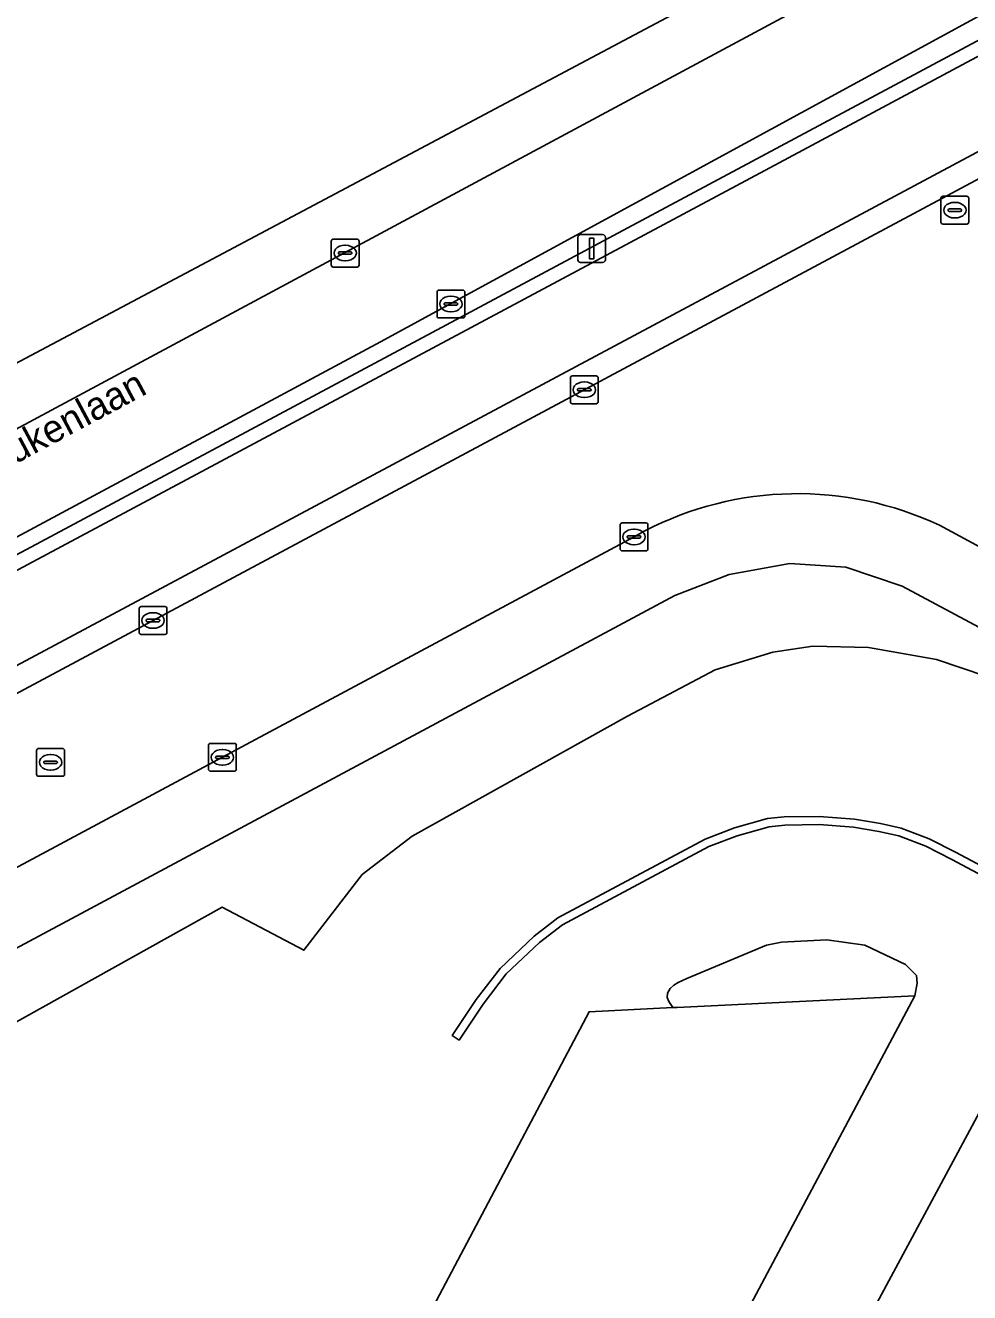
# Model space of a CAD drawing. Extents: x 159489 to 160304, y 383825 to 384531.
# Drawn here: x 159655.5 to 159689.39, y 384375.44 to 384420.89 of the extents above; entities that cross this region are included whole.
import ezdxf

# ---------------------------------------------------------------- set-up
doc = ezdxf.new("R2010")
doc.units = 0
for name, color, linetype in [('IMGEO_Berm_open', 7, 'Continuous'), ('IMGEO_Fietspad_gesloten', 7, 'Continuous'), ('IMGEO_Groenvoorziening', 7, 'Continuous'), ('IMGEO_Kolk', 7, 'Continuous'), ('IMGEO_Lichtmast', 7, 'Continuous'), ('IMGEO_Openbare_ruimte_label', 7, 'Continuous'), ('IMGEO_Parkeervlak_gesloten', 7, 'Continuous'), ('IMGEO_Rijbaan_lokaal_gesloten', 7, 'Continuous'), ('IMGEO_Rijbaan_lokaal_open', 7, 'Continuous'), ('IMGEO_Rijbaan_regionaal_gesloten', 7, 'Continuous'), ('IMGEO_Rioolput', 7, 'Continuous'), ('IMGEO_Verkeerseiland_open', 7, 'Continuous'), ('IMGEO_Voetpad_open', 7, 'Continuous')]:
    doc.layers.add(name, color=color, linetype=linetype)

msp = doc.modelspace()

# ---------------------------------------------------------------- linework, layer by layer
at = {"layer": 'IMGEO_Berm_open'}
for points in [[(159700.571, 384426.18), (159700.198, 384426.93), (159699.377, 384426.484), (159668.244, 384409.54), (159634.421, 384391.406), (159619.966, 384383.61), (159620.115, 384383.333), (159655.541, 384402.086)], [(159682.221, 384415.781), (159700.906, 384425.794), (159700.323, 384426.977), (159700.198, 384426.93), (159700.571, 384426.18), (159655.541, 384402.086), (159620.115, 384383.333), (159620.424, 384382.758), (159622.046, 384383.628)]]:
    msp.add_lwpolyline(points, close=True, dxfattribs=at)
at = {"layer": 'IMGEO_Fietspad_gesloten'}
for points in [[(159700.906, 384425.794), (159682.221, 384415.781), (159622.046, 384383.628), (159620.424, 384382.758), (159619.93, 384382.493), (159571.207, 384356.355), (159556.599, 384348.661)], [(159562.194, 384348.219), (159572.535, 384353.778), (159693.459, 384418.367)]]:
    msp.add_lwpolyline(points, dxfattribs=at)
at = {"layer": 'IMGEO_Groenvoorziening'}
for points in [[(159711.661, 384387.572), (159686.961, 384400.768), (159684.938, 384401.459), (159682.928, 384401.583), (159680.757, 384401.193), (159678.807, 384400.435), (159634.346, 384376.64)], [(159617.084, 384363.924), (159662.566, 384389.265), (159665.498, 384387.718), (159667.587, 384390.432), (159669.384, 384391.81), (159677.113, 384396.112), (159680.259, 384397.773), (159682.319, 384398.41), (159683.758, 384398.622), (159685.752, 384398.573), (159688.197, 384398.149), (159689.963, 384397.545)], [(159697.451, 384386.675), (159688.879, 384391.235), (159687.93, 384391.716), (159686.929, 384392.101), (159686.185, 384392.267), (159685.248, 384392.421), (159683.99, 384392.517), (159682.735, 384392.498), (159682.132, 384392.44), (159680.952, 384392.107), (159679.9, 384391.703), (159674.611, 384388.882), (159673.759, 384388.225), (159672.537, 384387.065), (159671.685, 384385.957), (159670.821, 384384.662), (159671.067, 384384.497), (159671.926, 384385.785), (159672.758, 384386.867), (159673.951, 384388), (159674.772, 384388.632), (159680.023, 384391.433), (159681.045, 384391.826), (159682.187, 384392.148), (159682.752, 384392.202), (159683.981, 384392.221), (159685.213, 384392.127), (159686.128, 384391.977), (159686.843, 384391.816), (159687.809, 384391.445), (159688.743, 384390.972), (159697.314, 384386.412)]]:
    msp.add_lwpolyline(points, dxfattribs=at)
msp.add_lwpolyline([(159678.738, 384385.659), (159678.896, 384385.666), (159687.417, 384386.081), (159687.504, 384386.535), (159687.473, 384386.812), (159687.089, 384387.211), (159685.628, 384387.905), (159684.258, 384388.086), (159682.637, 384388.006), (159682.093, 384387.895), (159679.238, 384386.705), (159679.078, 384386.638), (159678.921, 384386.562), (159678.766, 384386.466), (159678.634, 384386.35), (159678.539, 384386.183), (159678.535, 384386.023), (159678.59, 384385.88)], close=True, dxfattribs=at)
at = {"layer": 'IMGEO_Kolk'}
for p, q in [((159670.274, 384410.465), (159670.274, 384411.317)), ((159670.349, 384411.391), (159671.201, 384411.391)), ((159671.275, 384411.317), (159671.275, 384410.465)), ((159670.533, 384410.885), (159670.533, 384410.897)), ((159670.971, 384410.848), (159670.573, 384410.848)), ((159670.576, 384410.934), (159670.974, 384410.934)), ((159670.762, 384411.171), (159670.787, 384411.171)), ((159671.017, 384410.897), (159671.017, 384410.885)), ((159671.201, 384410.391), (159670.349, 384410.391)), ((159670.785, 384410.611), (159670.76, 384410.611)), ((159675.058, 384407.39), (159675.058, 384408.242)), ((159675.133, 384408.316), (159675.985, 384408.316)), ((159676.059, 384408.242), (159676.059, 384407.39)), ((159675.317, 384407.81), (159675.317, 384407.822)), ((159675.755, 384407.773), (159675.357, 384407.773)), ((159675.36, 384407.859), (159675.758, 384407.859)), ((159675.546, 384408.096), (159675.571, 384408.096)), ((159675.801, 384407.822), (159675.801, 384407.81)), ((159675.985, 384407.316), (159675.133, 384407.316)), ((159675.569, 384407.536), (159675.544, 384407.536)), ((159676.842, 384402.113), (159676.842, 384402.965)), ((159676.917, 384403.039), (159677.769, 384403.039)), ((159677.33, 384402.819), (159677.355, 384402.819)), ((159677.843, 384402.965), (159677.843, 384402.113)), ((159677.101, 384402.533), (159677.101, 384402.545)), ((159677.539, 384402.496), (159677.141, 384402.496)), ((159677.144, 384402.582), (159677.542, 384402.582)), ((159677.353, 384402.259), (159677.328, 384402.259)), ((159677.585, 384402.545), (159677.585, 384402.533)), ((159677.769, 384402.039), (159676.917, 384402.039)), ((159659.584, 384399.116), (159659.584, 384399.968)), ((159659.659, 384400.042), (159660.511, 384400.042)), ((159660.585, 384399.968), (159660.585, 384399.116)), ((159659.843, 384399.536), (159659.843, 384399.548)), ((159660.281, 384399.499), (159659.883, 384399.499)), ((159659.886, 384399.585), (159660.284, 384399.585)), ((159660.072, 384399.822), (159660.097, 384399.822)), ((159660.327, 384399.548), (159660.327, 384399.536)), ((159660.511, 384399.042), (159659.659, 384399.042)), ((159660.095, 384399.262), (159660.07, 384399.262)), ((159662.073, 384394.21), (159662.073, 384395.062)), ((159662.148, 384395.136), (159663, 384395.136)), ((159663.074, 384395.062), (159663.074, 384394.21)), ((159662.332, 384394.63), (159662.332, 384394.642)), ((159662.77, 384394.593), (159662.372, 384394.593)), ((159662.375, 384394.679), (159662.773, 384394.679)), ((159662.561, 384394.916), (159662.586, 384394.916)), ((159662.816, 384394.642), (159662.816, 384394.63)), ((159663, 384394.136), (159662.148, 384394.136)), ((159662.584, 384394.356), (159662.559, 384394.356))]:
    msp.add_line(p, q, dxfattribs=at)
for points in [[(159670.274, 384410.465), (159670.274, 384411.317)], [(159670.349, 384411.391), (159671.201, 384411.391)], [(159671.275, 384411.317), (159671.275, 384410.465)], [(159671.201, 384410.391), (159670.349, 384410.391)], [(159675.058, 384407.39), (159675.058, 384408.242)], [(159675.133, 384408.316), (159675.985, 384408.316)], [(159676.059, 384408.242), (159676.059, 384407.39)], [(159675.985, 384407.316), (159675.133, 384407.316)], [(159676.842, 384402.113), (159676.842, 384402.965)], [(159676.917, 384403.039), (159677.769, 384403.039)], [(159677.843, 384402.965), (159677.843, 384402.113)], [(159677.769, 384402.039), (159676.917, 384402.039)], [(159659.584, 384399.116), (159659.584, 384399.968)], [(159659.659, 384400.042), (159660.511, 384400.042)], [(159660.585, 384399.968), (159660.585, 384399.116)], [(159660.511, 384399.042), (159659.659, 384399.042)], [(159662.073, 384394.21), (159662.073, 384395.062)], [(159662.148, 384395.136), (159663, 384395.136)], [(159663.074, 384395.062), (159663.074, 384394.21)], [(159663, 384394.136), (159662.148, 384394.136)]]:
    msp.add_lwpolyline(points, dxfattribs=at)
for centre, radius, start, end in [((159670.351, 384411.315), 0.0765, 91.552, 178.448), ((159670.351, 384411.315), 0.0765, 91.552, 178.448), ((159671.199, 384411.315), 0.0765, 1.552, 88.448), ((159671.199, 384411.315), 0.0765, 1.552, 88.448), ((159670.573, 384410.894), 0.0403, 85.8775, 175.7526), ((159670.57, 384410.884), 0.0366, 178.938, 274.7102), ((159670.974, 384410.891), 0.043, 264.8664, 352.4533), ((159670.978, 384410.896), 0.0386, 1.7309, 96.639), ((159670.351, 384410.467), 0.0765, 181.552, 268.448), ((159670.351, 384410.467), 0.0765, 181.552, 268.448), ((159671.199, 384410.467), 0.0765, 271.552, 358.448), ((159671.199, 384410.467), 0.0765, 271.552, 358.448), ((159675.135, 384408.24), 0.0765, 91.552, 178.448), ((159675.135, 384408.24), 0.0765, 91.552, 178.448), ((159675.983, 384408.24), 0.0765, 1.552, 88.448), ((159675.983, 384408.24), 0.0765, 1.552, 88.448), ((159675.357, 384407.819), 0.0403, 85.8775, 175.7526), ((159675.354, 384407.809), 0.0366, 178.938, 274.7102), ((159675.758, 384407.816), 0.043, 264.8664, 352.4533), ((159675.762, 384407.821), 0.0386, 1.7309, 96.639), ((159675.135, 384407.392), 0.0765, 181.552, 268.448), ((159675.135, 384407.392), 0.0765, 181.552, 268.448), ((159675.983, 384407.392), 0.0765, 271.552, 358.448), ((159675.983, 384407.392), 0.0765, 271.552, 358.448), ((159676.919, 384402.963), 0.0765, 91.552, 178.448), ((159676.919, 384402.963), 0.0765, 91.552, 178.448), ((159677.767, 384402.963), 0.0765, 1.552, 88.448), ((159677.767, 384402.963), 0.0765, 1.552, 88.448), ((159677.141, 384402.542), 0.0403, 85.8775, 175.7526), ((159677.138, 384402.532), 0.0366, 178.938, 274.7102), ((159677.542, 384402.539), 0.043, 264.8664, 352.4533), ((159677.546, 384402.544), 0.0386, 1.7309, 96.639), ((159676.919, 384402.115), 0.0765, 181.552, 268.448), ((159676.919, 384402.115), 0.0765, 181.552, 268.448), ((159677.767, 384402.115), 0.0765, 271.552, 358.448), ((159677.767, 384402.115), 0.0765, 271.552, 358.448), ((159659.661, 384399.966), 0.0765, 91.552, 178.448), ((159659.661, 384399.966), 0.0765, 91.552, 178.448), ((159660.509, 384399.966), 0.0765, 1.552, 88.448), ((159660.509, 384399.966), 0.0765, 1.552, 88.448), ((159659.883, 384399.545), 0.0403, 85.8775, 175.7526), ((159659.88, 384399.535), 0.0366, 178.938, 274.7102), ((159660.284, 384399.542), 0.043, 264.8664, 352.4533), ((159660.288, 384399.547), 0.0386, 1.7309, 96.639), ((159659.661, 384399.118), 0.0765, 181.552, 268.448), ((159659.661, 384399.118), 0.0765, 181.552, 268.448), ((159660.509, 384399.118), 0.0765, 271.552, 358.448), ((159660.509, 384399.118), 0.0765, 271.552, 358.448), ((159662.15, 384395.06), 0.0765, 91.552, 178.448), ((159662.15, 384395.06), 0.0765, 91.552, 178.448), ((159662.998, 384395.06), 0.0765, 1.552, 88.448), ((159662.998, 384395.06), 0.0765, 1.552, 88.448), ((159662.372, 384394.639), 0.0403, 85.8775, 175.7526), ((159662.369, 384394.629), 0.0366, 178.938, 274.7102), ((159662.773, 384394.636), 0.043, 264.8664, 352.4533), ((159662.777, 384394.641), 0.0386, 1.7309, 96.639), ((159662.15, 384394.212), 0.0765, 181.552, 268.448), ((159662.15, 384394.212), 0.0765, 181.552, 268.448), ((159662.998, 384394.212), 0.0765, 271.552, 358.448), ((159662.998, 384394.212), 0.0765, 271.552, 358.448)]:
    msp.add_arc(centre, radius, start, end, dxfattribs=at)
for centre, major_axis, ratio, start_param, end_param in [((159670.761, 384410.891), (-0.387, 0.002), 0.722429, 4.712389, 7.853982), ((159670.786, 384410.891), (-0.39, 0.002), 0.717154, 1.570796, 4.712389), ((159675.545, 384407.816), (-0.387, 0.002), 0.722429, 4.712389, 7.853982), ((159675.57, 384407.816), (-0.39, 0.002), 0.717154, 1.570796, 4.712389), ((159677.329, 384402.539), (-0.387, 0.002), 0.722429, 4.712389, 7.853982), ((159677.354, 384402.539), (-0.39, 0.002), 0.717154, 1.570796, 4.712389), ((159660.071, 384399.542), (-0.387, 0.002), 0.722429, 4.712389, 7.853982), ((159660.096, 384399.542), (-0.39, 0.002), 0.717154, 1.570796, 4.712389), ((159662.56, 384394.636), (-0.387, 0.002), 0.722429, 4.712389, 7.853982), ((159662.585, 384394.636), (-0.39, 0.002), 0.717154, 1.570796, 4.712389)]:
    msp.add_ellipse(centre, major_axis=major_axis, ratio=ratio, start_param=start_param, end_param=end_param, dxfattribs=at)
at = {"layer": 'IMGEO_Lichtmast'}
for p, q in [((159675.326, 384412.482), (159675.326, 384413.282)), ((159675.326, 384413.282), (159675.326, 384412.482)), ((159675.426, 384413.382), (159676.216, 384413.382)), ((159676.216, 384413.382), (159675.426, 384413.382)), ((159676.316, 384413.282), (159676.316, 384412.482)), ((159676.316, 384412.482), (159676.316, 384413.282)), ((159676.216, 384412.382), (159675.426, 384412.382)), ((159675.426, 384412.382), (159676.216, 384412.382))]:
    msp.add_line(p, q, dxfattribs=at)
msp.add_lwpolyline([(159675.746, 384413.257), (159675.896, 384413.257), (159675.896, 384412.507), (159675.746, 384412.507), (159675.746, 384413.257)], dxfattribs=at)
for centre, start, end in [((159675.426, 384413.282), 90, 180), ((159675.426, 384413.282), 90, 180), ((159676.216, 384413.282), 0, 90), ((159676.216, 384413.282), 360, 90), ((159675.426, 384412.482), 180, 270), ((159675.426, 384412.482), 180, 270), ((159676.216, 384412.482), 270, 0), ((159676.216, 384412.482), 270, 0)]:
    msp.add_arc(centre, 0.1, start, end, dxfattribs=at)
at = {"layer": 'IMGEO_Parkeervlak_gesloten'}
for points in [[(159687.417, 384386.081), (159678.896, 384385.666), (159678.738, 384385.659), (159675.733, 384385.513), (159665.311, 384365.821), (159665.072, 384365.355), (159669.77, 384365.497), (159670.746, 384365.527), (159669.452, 384363.069), (159675.243, 384363.209)], [(159698.84, 384377.821), (159695.932, 384382.421), (159695.678, 384382.553), (159694.411, 384380.114), (159691.369, 384384.932), (159677.739, 384359.604), (159682.548, 384352.155), (159683.929, 384350.016)]]:
    msp.add_lwpolyline(points, close=True, dxfattribs=at)
at = {"layer": 'IMGEO_Rijbaan_lokaal_gesloten'}
for points in [[(159696.183, 384418.774), (159693.863, 384417.603), (159580.529, 384357.003), (159566.867, 384349.736)], [(159688.298, 384402.957), (159693.987, 384399.894), (159694.131, 384399.817), (159697.176, 384404.382)], [(159634.128, 384379.44), (159639.03, 384381.993), (159649.269, 384387.523), (159662.574, 384394.636), (159677.343, 384402.539), (159677.726, 384402.756)]]:
    msp.add_lwpolyline(points, dxfattribs=at)
msp.add_arc((159683.216, 384392.14), 11.952, 64.8347, 117.3437, dxfattribs=at)
at = {"layer": 'IMGEO_Rijbaan_lokaal_open'}
for points in [[(159689.963, 384397.545), (159688.197, 384398.149), (159685.752, 384398.573), (159683.758, 384398.622), (159682.319, 384398.41), (159680.259, 384397.773), (159677.113, 384396.112), (159669.384, 384391.81), (159667.587, 384390.432), (159665.498, 384387.718), (159662.566, 384389.265), (159617.084, 384363.924)], [(159697.314, 384386.412), (159688.743, 384390.972), (159687.809, 384391.445), (159686.843, 384391.816), (159686.128, 384391.977), (159685.213, 384392.127), (159683.981, 384392.221), (159682.752, 384392.202), (159682.187, 384392.148), (159681.045, 384391.826), (159680.023, 384391.433), (159674.772, 384388.632), (159673.951, 384388), (159672.758, 384386.867), (159671.926, 384385.785), (159671.067, 384384.497), (159670.821, 384384.662), (159671.685, 384385.957), (159672.537, 384387.065), (159673.759, 384388.225), (159674.611, 384388.882), (159679.9, 384391.703), (159680.952, 384392.107), (159682.132, 384392.44), (159682.735, 384392.498), (159683.99, 384392.517), (159685.248, 384392.421), (159686.185, 384392.267), (159686.929, 384392.101), (159687.93, 384391.716), (159688.879, 384391.235), (159697.451, 384386.675)], [(159665.311, 384365.821), (159675.733, 384385.513), (159678.738, 384385.659), (159678.59, 384385.88), (159678.535, 384386.023), (159678.539, 384386.183), (159678.634, 384386.35), (159678.766, 384386.466), (159678.921, 384386.562), (159679.078, 384386.638), (159679.238, 384386.705), (159682.093, 384387.895), (159682.637, 384388.006), (159684.258, 384388.086), (159685.628, 384387.905), (159687.089, 384387.211), (159687.473, 384386.812), (159687.504, 384386.535), (159687.417, 384386.081), (159675.243, 384363.209)]]:
    msp.add_lwpolyline(points, dxfattribs=at)
msp.add_lwpolyline([(159691.369, 384384.932), (159695.678, 384382.553), (159695.932, 384382.421), (159698.08, 384381.33), (159698.461, 384381.082), (159698.767, 384380.821), (159699.117, 384380.297), (159699.236, 384380.001), (159699.314, 384379.655), (159699.302, 384379.126), (159699.195, 384378.691), (159699.032, 384378.256), (159698.84, 384377.821), (159683.929, 384350.016), (159682.548, 384352.155), (159682.228, 384351.922), (159678.065, 384356.505), (159677.918, 384356.933), (159677.785, 384357.366), (159677.677, 384357.808), (159677.604, 384358.26), (159677.584, 384358.715), (159677.632, 384359.163), (159677.739, 384359.604)], close=True, dxfattribs=at)
at = {"layer": 'IMGEO_Rijbaan_regionaal_gesloten'}
msp.add_lwpolyline([(159617.271, 384388.641), (159618.33, 384386.664), (159630.055, 384392.935), (159696.891, 384428.803), (159718.831, 384440.572), (159756.87, 384460.87), (159792.184, 384479.496), (159799.29, 384483.122), (159806.379, 384486.798), (159827.767, 384497.696), (159874.847, 384521.573), (159884.805, 384526.627), (159885.682, 384527.066), (159884.047, 384528.944), (159756.881, 384462.779), (159617.372, 384388.695)], close=True, dxfattribs=at)
msp.add_lwpolyline([(159792.184, 384479.496), (159756.87, 384460.87), (159718.831, 384440.572), (159696.891, 384428.803), (159630.055, 384392.935), (159618.33, 384386.664), (159619.966, 384383.61), (159634.421, 384391.406), (159668.244, 384409.54), (159699.377, 384426.484), (159700.751, 384427.559), (159703.495, 384429.013), (159710.497, 384432.75), (159717.537, 384436.529), (159724.53, 384440.318), (159731.586, 384444.059), (159738.618, 384447.846), (159745.626, 384451.551), (159752.717, 384455.366), (159759.792, 384459.11), (159766.895, 384462.87), (159770.258, 384464.683)], dxfattribs=at)
at = {"layer": 'IMGEO_Rioolput'}
for p, q in [((159688.354, 384413.831), (159688.354, 384414.683)), ((159688.429, 384414.757), (159689.281, 384414.757)), ((159688.842, 384414.537), (159688.867, 384414.537)), ((159689.355, 384414.683), (159689.355, 384413.831)), ((159688.613, 384414.251), (159688.613, 384414.263)), ((159689.051, 384414.214), (159688.653, 384414.214)), ((159688.656, 384414.3), (159689.054, 384414.3)), ((159689.097, 384414.263), (159689.097, 384414.251)), ((159689.281, 384413.757), (159688.429, 384413.757)), ((159688.865, 384413.977), (159688.84, 384413.977)), ((159666.479, 384412.293), (159666.479, 384413.145)), ((159666.554, 384413.219), (159667.406, 384413.219)), ((159667.48, 384413.145), (159667.48, 384412.293)), ((159666.738, 384412.713), (159666.738, 384412.725)), ((159667.176, 384412.676), (159666.778, 384412.676)), ((159666.781, 384412.762), (159667.179, 384412.762)), ((159666.967, 384412.999), (159666.992, 384412.999)), ((159667.222, 384412.725), (159667.222, 384412.713)), ((159667.406, 384412.219), (159666.554, 384412.219)), ((159666.99, 384412.439), (159666.965, 384412.439)), ((159655.985, 384394.955), (159656.837, 384394.955)), ((159655.91, 384394.029), (159655.91, 384394.881)), ((159656.212, 384394.498), (159656.61, 384394.498)), ((159656.398, 384394.735), (159656.423, 384394.735)), ((159656.911, 384394.881), (159656.911, 384394.029)), ((159656.169, 384394.449), (159656.169, 384394.461)), ((159656.607, 384394.412), (159656.209, 384394.412)), ((159656.421, 384394.175), (159656.396, 384394.175)), ((159656.653, 384394.461), (159656.653, 384394.449)), ((159656.837, 384393.955), (159655.985, 384393.955))]:
    msp.add_line(p, q, dxfattribs=at)
for points in [[(159688.354, 384413.831), (159688.354, 384414.683)], [(159688.429, 384414.757), (159689.281, 384414.757)], [(159689.355, 384414.683), (159689.355, 384413.831)], [(159689.281, 384413.757), (159688.429, 384413.757)], [(159666.479, 384412.293), (159666.479, 384413.145)], [(159666.554, 384413.219), (159667.406, 384413.219)], [(159667.48, 384413.145), (159667.48, 384412.293)], [(159667.406, 384412.219), (159666.554, 384412.219)], [(159655.985, 384394.955), (159656.837, 384394.955)], [(159655.91, 384394.029), (159655.91, 384394.881)], [(159656.911, 384394.881), (159656.911, 384394.029)], [(159656.837, 384393.955), (159655.985, 384393.955)]]:
    msp.add_lwpolyline(points, dxfattribs=at)
for centre, radius, start, end in [((159688.431, 384414.681), 0.0765, 91.552, 178.448), ((159688.431, 384414.681), 0.0765, 91.552, 178.448), ((159689.279, 384414.681), 0.0765, 1.552, 88.448), ((159689.279, 384414.681), 0.0765, 1.552, 88.448), ((159688.653, 384414.26), 0.0403, 85.8775, 175.7526), ((159688.65, 384414.25), 0.0366, 178.938, 274.7102), ((159689.054, 384414.257), 0.043, 264.8664, 352.4533), ((159689.058, 384414.262), 0.0386, 1.7309, 96.639), ((159688.431, 384413.833), 0.0765, 181.552, 268.448), ((159688.431, 384413.833), 0.0765, 181.552, 268.448), ((159689.279, 384413.833), 0.0765, 271.552, 358.448), ((159689.279, 384413.833), 0.0765, 271.552, 358.448), ((159666.556, 384413.143), 0.0765, 91.552, 178.448), ((159666.556, 384413.143), 0.0765, 91.552, 178.448), ((159667.404, 384413.143), 0.0765, 1.552, 88.448), ((159667.404, 384413.143), 0.0765, 1.552, 88.448), ((159666.778, 384412.722), 0.0403, 85.8775, 175.7526), ((159666.775, 384412.712), 0.0366, 178.938, 274.7102), ((159667.179, 384412.719), 0.043, 264.8664, 352.4533), ((159667.183, 384412.724), 0.0386, 1.7309, 96.639), ((159666.556, 384412.295), 0.0765, 181.552, 268.448), ((159666.556, 384412.295), 0.0765, 181.552, 268.448), ((159667.404, 384412.295), 0.0765, 271.552, 358.448), ((159667.404, 384412.295), 0.0765, 271.552, 358.448), ((159655.987, 384394.879), 0.0765, 91.552, 178.448), ((159655.987, 384394.879), 0.0765, 91.552, 178.448), ((159656.835, 384394.879), 0.0765, 1.552, 88.448), ((159656.835, 384394.879), 0.0765, 1.552, 88.448), ((159656.209, 384394.458), 0.0403, 85.8775, 175.7526), ((159656.614, 384394.46), 0.0386, 1.7309, 96.639), ((159655.987, 384394.031), 0.0765, 181.552, 268.448), ((159655.987, 384394.031), 0.0765, 181.552, 268.448), ((159656.206, 384394.448), 0.0366, 178.938, 274.7102), ((159656.61, 384394.455), 0.043, 264.8664, 352.4533), ((159656.835, 384394.031), 0.0765, 271.552, 358.448), ((159656.835, 384394.031), 0.0765, 271.552, 358.448)]:
    msp.add_arc(centre, radius, start, end, dxfattribs=at)
for centre, major_axis, ratio, start_param, end_param in [((159688.841, 384414.257), (-0.387, 0.002), 0.722429, 4.712389, 7.853982), ((159688.866, 384414.257), (-0.39, 0.002), 0.717154, 1.570796, 4.712389), ((159666.966, 384412.719), (-0.387, 0.002), 0.722429, 4.712389, 7.853982), ((159666.991, 384412.719), (-0.39, 0.002), 0.717154, 1.570796, 4.712389), ((159656.397, 384394.455), (-0.387, 0.002), 0.722429, 4.712389, 7.853982), ((159656.422, 384394.455), (-0.39, 0.002), 0.717154, 1.570796, 4.712389)]:
    msp.add_ellipse(centre, major_axis=major_axis, ratio=ratio, start_param=start_param, end_param=end_param, dxfattribs=at)
at = {"layer": 'IMGEO_Verkeerseiland_open'}
for points in [[(159693.863, 384417.603), (159693.459, 384418.367), (159572.535, 384353.778), (159562.194, 384348.219)], [(159566.867, 384349.736), (159580.529, 384357.003), (159693.863, 384417.603)]]:
    msp.add_lwpolyline(points, dxfattribs=at)
at = {"layer": 'IMGEO_Voetpad_open'}
for points in [[(159677.726, 384402.756), (159677.343, 384402.539), (159662.574, 384394.636), (159649.269, 384387.523), (159639.03, 384381.993), (159634.128, 384379.44), (159633.124, 384378.917), (159633.379, 384378.441), (159634.346, 384376.64), (159678.807, 384400.435), (159680.757, 384401.193), (159682.928, 384401.583), (159684.938, 384401.459), (159686.961, 384400.768), (159711.661, 384387.572), (159712.503, 384386.97), (159713.102, 384385.975), (159713.006, 384384.347), (159712.165, 384382.809)], [(159713.402, 384389.552), (159712.599, 384389.972), (159694.131, 384399.817), (159693.987, 384399.894), (159688.298, 384402.957)]]:
    msp.add_lwpolyline(points, dxfattribs=at)
msp.add_arc((159683.216, 384392.14), 11.952, 64.8347, 117.3437, dxfattribs=at)

# ---------------------------------------------------------------- texts
at = {"layer": 'IMGEO_Openbare_ruimte_label'}
msp.add_text('Beukenlaan', height=1, rotation=28.1028, dxfattribs=at).set_placement((159653.693, 384404.368))

doc.saveas('drawing.dxf')
